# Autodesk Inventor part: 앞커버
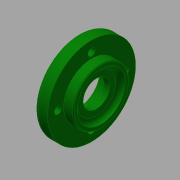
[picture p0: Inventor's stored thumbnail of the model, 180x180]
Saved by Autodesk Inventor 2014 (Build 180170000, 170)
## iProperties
Created: 2015-12
Part Number: 앞커버
Material: 알루미늄 6061
Document SubType Name: Modeling
Designer: mduedu
Density: 2.71 g/cm^3
Appearance: 진녹색
Author: mduedu
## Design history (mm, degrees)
sketch "스케치1"
  geometry: L1 (0, 0)-(14, 0); L2 (14, 0)-(14, 17.5); L3 (14, 17.5)-(8, 17.5); L4 (8, 17.5)-(8, 27.5); L5 (8, 27.5)-(0, 27.5); L6 (0, 27.5)-(0, 0)
  constraints: 12 end point, 4 parallel, 1 horizontal, 1 perpendicular
  dimensions: "d0" = 14 distance between parallel lines of L2 L6; "d2" = 8 distance of L4.end L5.end; "d3" = 55 diameter of L5 L1; "d4" = 35 diameter of L3 L1
revolve "회전1" sketch "스케치1" stored, may be unused: angle "d5" = 90 deg
hole "구멍1" diameter "d8" = 30; stored, may be unused: countersink angle "d12" = 90 deg, drill point angle "d14" = 0 deg; dims "d6" = 10, "d7" = 10, "d9" = 6, "d10" = 4, "d11" = 2, "d13" = 3
hole "구멍2" diameter "d17" = 25; stored, may be unused: countersink angle "d21" = 90 deg, drill point angle "d23" = 0 deg; dims "d15" = 10, "d16" = 10, "d18" = 6, "d19" = 4, "d20" = 2, "d22" = 7.3
hole "구멍3" diameter "d26" = 16.5; stored, may be unused: countersink angle "d30" = 90 deg, drill point angle "d32" = 0 deg; dims "d24" = 10, "d25" = 10, "d27" = 6, "d28" = 4, "d29" = 2, "d31" = 7.3
fillet "모깎기1" dims "d33" = 0.3
chamfer "모따기1" distance "d34" = 1; stored, may be unused: second distance "d35" = 2, angle "d36" = 30 deg
fillet "모깎기2" dims "d37" = 3
fillet "모깎기3" dims "d38" = 2
chamfer "모따기2" distance "d39" = 0.5; stored, may be unused: second distance "d40" = 2, angle "d41" = 45 deg
sketch "스케치2" dims "d42" = 42
  geometry: 9 further points
  constraints: 3 coincident, 2 vertical alignment, 9 other
  dimensions: "d46" = 360 deg dimension on point (0, 0) point (0, 21) (derived)
sketch "스케치3"
  geometry: 4 further points
hole "구멍4" sketch "스케치3" at (-21, 0), (0, -21), (21, 0), (0, 21) diameter "d50" = 4.5; stored, may be unused: countersink angle "d54" = 90 deg, drill point angle "d56" = 0 deg; dims "d51" = 6, "d52" = 8, "d53" = 4.6, "d55" = 8
node "솔리드1"
